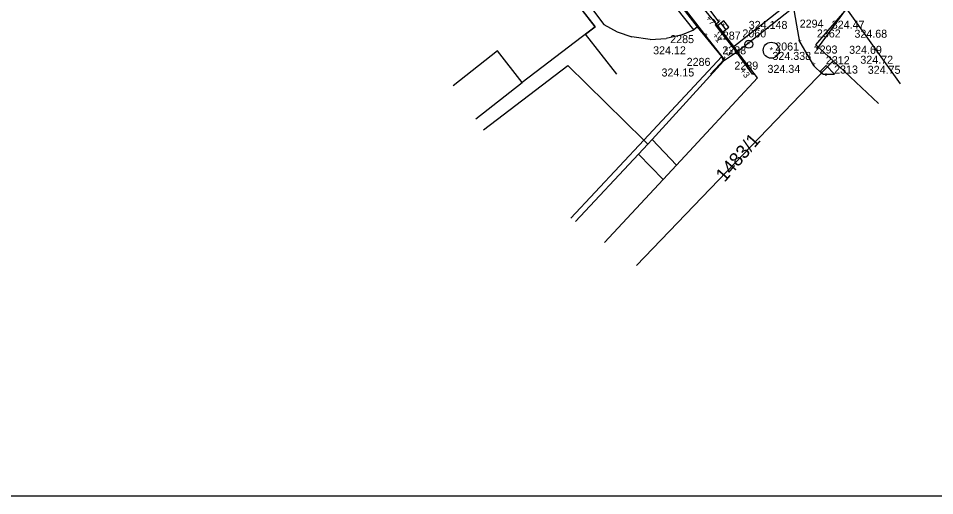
# Model space of a CAD drawing. Extents: x -600587 to -600377, y -1159886 to -1159708.
# Drawn here: x -600539.9 to -600482.7, y -1159886.4 to -1159856.5 of the extents above; entities that cross this region are included whole.
import ezdxf

# ---------------------------------------------------------------- set-up
doc = ezdxf.new("R2010")
doc.units = 0
for name, color, linetype in [('Hranice parcel', 7, 'Continuous'), ('Level 24', 7, 'Continuous'), ('Level 27', 7, 'Continuous'), ('Parcelní čísla', 7, 'Continuous'), ('Vnitřní kresba', 7, 'Continuous'), ('Vrstva 10', 7, 'Continuous'), ('Vrstva 11', 7, 'Continuous'), ('Vrstva 16', 7, 'Continuous'), ('Vrstva 2', 7, 'Continuous'), ('Vrstva 20', 7, 'Continuous'), ('Vrstva 58', 7, 'Continuous'), ('Vrstva 59', 7, 'Continuous'), ('Vrstva 6', 7, 'Continuous'), ('Vrstva 60', 7, 'Continuous'), ('Vrstva 7', 7, 'Continuous')]:
    doc.layers.add(name, color=color, linetype=linetype)

msp = doc.modelspace()

# ---------------------------------------------------------------- linework, layer by layer
at = {"layer": 'Hranice parcel'}
for p, q in [((-600489.18, -1159854.01), (-600495, -1159858.63)), ((-600495, -1159858.63), (-600495.86, -1159859.22)), ((-600501.292, -1159871.979), (-600489.02, -1159859.21)), ((-600486.174, -1159861.872), (-600489.02, -1159859.21))]:
    msp.add_line(p, q, dxfattribs=at)
for points in [[(-600495.86, -1159859.22), (-600495.98, -1159858.93), (-600497.49, -1159857.08), (-600508.85, -1159842.47)], [(-600488.61, -1159847.98), (-600491.1, -1159850.3), (-600496.53, -1159855.35), (-600497.15, -1159855.9), (-600496.12, -1159857.16), (-600495, -1159858.63)], [(-600489.02, -1159859.21), (-600490.1, -1159858.2), (-600488.17, -1159855.96)], [(-600484.806, -1159860.645), (-600488.17, -1159855.96)], [(-600510.85, -1159863.508), (-600505.59, -1159859.5), (-600500.85, -1159864.15), (-600500.59, -1159864.41)], [(-600495.86, -1159859.22), (-600500.32, -1159864.11), (-600500.59, -1159864.41)], [(-600500.59, -1159864.41), (-600501.17, -1159865.04), (-600505.103, -1159869.237)]]:
    msp.add_lwpolyline(points, dxfattribs=at)
at = {"layer": 'Level 24'}
msp.add_line((-600489.632, -1159860.037), (-600488.929, -1159860.037), dxfattribs=at)
msp.add_lwpolyline([(-600488.929, -1159860.037), (-600489.458, -1159859.501), (-600489.814, -1159859.852), (-600489.632, -1159860.037)], dxfattribs=at)
at = {"layer": 'Level 27'}
msp.add_line((-600496.042, -1159856.857), (-600495.732, -1159857.249), dxfattribs=at)
msp.add_lwpolyline([(-600496.238, -1159857.013), (-600495.928, -1159857.404), (-600495.536, -1159857.094), (-600495.846, -1159856.702)], close=True, dxfattribs=at)
msp.add_circle((-600492.885, -1159858.54), 0.5, dxfattribs=at)
at = {"layer": 'Vnitřní kresba'}
for p, q in [((-600512.8, -1159845.57), (-600503.89, -1159857.08)), ((-600497.73, -1159857.27), (-600504.36, -1159848.76)), ((-600507.64, -1159851.25), (-600503.34, -1159856.93)), ((-600503.89, -1159857.08), (-600508.44, -1159860.56)), ((-600503.34, -1159856.93), (-600502.51, -1159857.4)), ((-600502.51, -1159857.4), (-600501.6, -1159857.71)), ((-600498.53, -1159857.6), (-600497.73, -1159857.27)), ((-600497.49, -1159857.08), (-600497.73, -1159857.27)), ((-600500.44, -1159857.86), (-600501.6, -1159857.71)), ((-600500.44, -1159857.86), (-600499.44, -1159857.81)), ((-600498.53, -1159857.6), (-600499.44, -1159857.81)), ((-600509.98, -1159858.57), (-600512.765, -1159860.763)), ((-600508.44, -1159860.56), (-600509.98, -1159858.57)), ((-600500.85, -1159864.15), (-600495.98, -1159858.93)), ((-600493.74, -1159860.26), (-600495, -1159858.63)), ((-600498.8, -1159865.71), (-600493.74, -1159860.26)), ((-600511.33, -1159862.82), (-600508.44, -1159860.56)), ((-600505.4, -1159869.024), (-600500.85, -1159864.15)), ((-600500.32, -1159864.11), (-600498.8, -1159865.71)), ((-600501.17, -1159865.04), (-600499.64, -1159866.62)), ((-600499.64, -1159866.62), (-600498.8, -1159865.71)), ((-600503.295, -1159870.539), (-600499.64, -1159866.62))]:
    msp.add_line(p, q, dxfattribs=at)
at = {"layer": 'Vrstva 10'}
msp.add_line((-600499.56, -1159854.317), (-600496.968, -1159857.663), dxfattribs=at)
at = {"layer": 'Vrstva 11'}
for p, q in [((-600498.297, -1159853.946), (-600496.159, -1159856.789)), ((-600491.557, -1159855.432), (-600495.283, -1159858.38)), ((-600491.107, -1159858.044), (-600491.557, -1159855.432)), ((-600490.033, -1159858.492), (-600487.688, -1159855.251)), ((-600495.906, -1159857.574), (-600495.283, -1159858.38)), ((-600495.283, -1159858.38), (-600494.072, -1159860.037)), ((-600491.107, -1159858.044), (-600490.234, -1159859.497)), ((-600490.234, -1159859.497), (-600489.681, -1159860.037))]:
    msp.add_line(p, q, dxfattribs=at)
msp.add_lwpolyline([(-600496.159, -1159856.789), (-600496.381, -1159856.963), (-600495.906, -1159857.574)], dxfattribs=at)
at = {"layer": 'Vrstva 2'}
msp.add_lwpolyline([(-600586.635, -1159886.355), (-600376.635, -1159886.355), (-600376.635, -1159737.855), (-600586.635, -1159737.855)], close=True, dxfattribs=at)
at = {"layer": 'Vrstva 20'}
msp.add_lwpolyline([(-600502.538, -1159860.037), (-600504.48, -1159857.53), (-600503.89, -1159857.08), (-600512.8, -1159845.57), (-600520.767, -1159851.79)], dxfattribs=at)
at = {"layer": 'Vrstva 6'}
msp.add_circle((-600494.29, -1159858.169), 0.25, dxfattribs=at)
at = {"layer": 'Vrstva 7'}
for p, q in [((-600496.968, -1159857.663), (-600495.822, -1159859.118)), ((-600495.822, -1159859.118), (-600496.681, -1159860.037))]:
    msp.add_line(p, q, dxfattribs=at)

# ---------------------------------------------------------------- texts
at = {"layer": 'Parcelní čísla'}
msp.add_text('1483/1', height=0.85, rotation=49, dxfattribs=at).set_placement((-600495.797, -1159866.82))
at = {"layer": 'Vrstva 16'}
for s, p in [('+7', (-600497.006, -1159856.552)), ('+1', (-600496.593, -1159857.634)), ('+3', (-600495.934, -1159858.454)), ('+3', (-600494.873, -1159859.838))]:
    msp.add_text(s, height=0.4, rotation=308.3679, dxfattribs=at).set_placement(p)
at = {"layer": 'Vrstva 58'}
for s, p in [('324.148', (-600494.29, -1159857.21)), ('324.47', (-600489.102, -1159857.195)), ('324.68', (-600487.688, -1159857.76)), ('324.12', (-600500.263, -1159858.796)), ('324.69', (-600488.018, -1159858.765)), ('324.338', (-600492.809, -1159859.145)), ('324.72', (-600487.318, -1159859.384)), ('324.15', (-600499.739, -1159860.18)), ('324.34', (-600493.119, -1159859.955)), ('324.75', (-600486.856, -1159860.013))]:
    msp.add_text(s, height=0.5, dxfattribs=at).set_placement(p)
at = {"layer": 'Vrstva 59'}
for s, p in [('2294', (-600491.107, -1159857.13)), ('2287', (-600496.281, -1159857.877)), ('2060', (-600494.689, -1159857.741)), ('2362', (-600490.033, -1159857.742)), ('2285', (-600499.196, -1159858.097)), ('2288', (-600495.94, -1159858.797)), ('2061', (-600492.633, -1159858.558)), ('2293', (-600490.234, -1159858.747)), ('2286', (-600498.167, -1159859.517)), ('2312', (-600489.47, -1159859.413)), ('2289', (-600495.187, -1159859.749)), ('2313', (-600488.955, -1159859.995))]:
    msp.add_text(s, height=0.5, dxfattribs=at).set_placement(p)
at = {"layer": 'Vrstva 60'}
for p in [(-600496.257, -1159856.989), (-600496.004, -1159857.774), (-600495.986, -1159857.252), (-600497.066, -1159857.863), (-600494.388, -1159858.369), (-600491.205, -1159858.244), (-600495.381, -1159858.58), (-600492.983, -1159858.74), (-600490.131, -1159858.692), (-600495.92, -1159859.318), (-600490.332, -1159859.697), (-600494.132, -1159860.289), (-600489.568, -1159860.363)]:
    msp.add_text('*', height=0.4, dxfattribs=at).set_placement(p)

doc.saveas('drawing.dxf')
